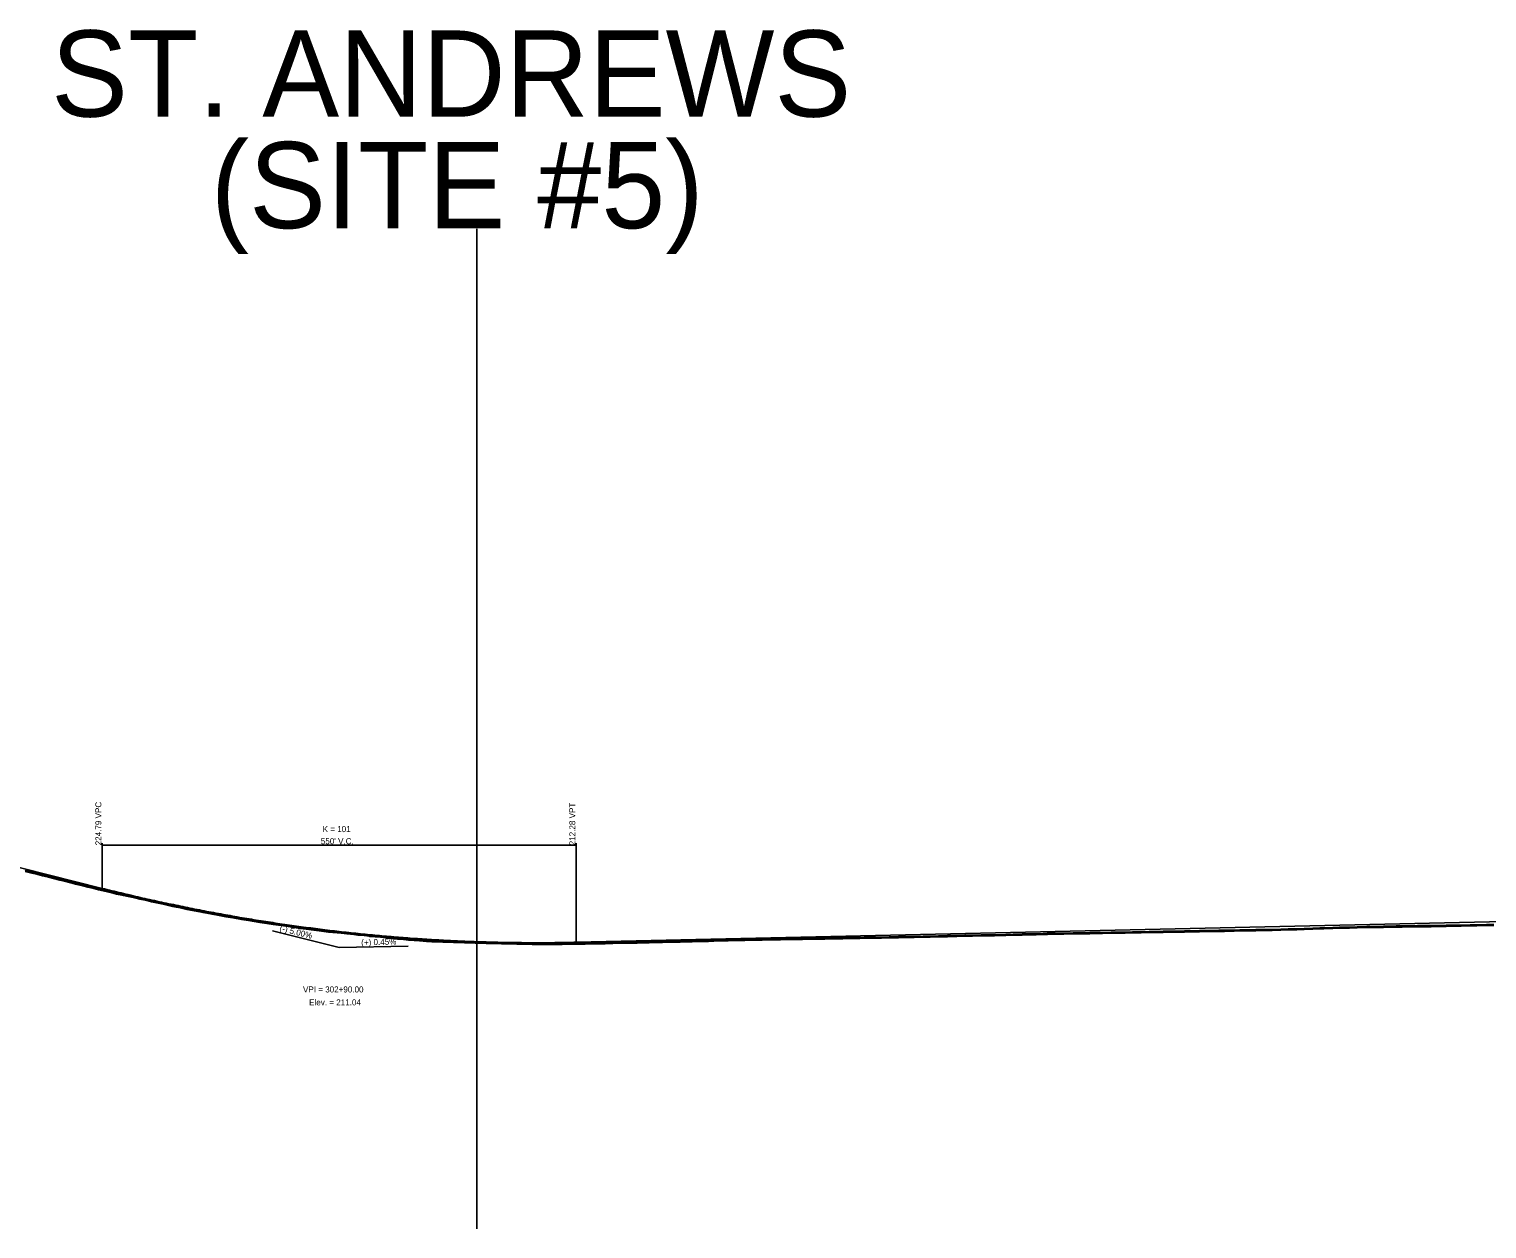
# Model space of a CAD drawing. Extents: x 1876258 to 1926563, y 729739 to 834437.
# Drawn here: x 1908293 to 1909985, y 830733 to 832125 of the extents above; entities that cross this region are included whole.
import ezdxf

# ---------------------------------------------------------------- set-up
doc = ezdxf.new("R2010")
doc.units = 0
for name, color, linetype in [('RD_EX_BldgApp', 7, 'Continuous'), ('RD_EX_H2O_BlueLn', 7, 'Continuous'), ('RD_EX_RailRoad', 7, 'Continuous'), ('RD_HC_Data', 7, 'Continuous'), ('RD_HC_Data_Tic', 7, 'Continuous'), ('RD_HC_TX_Sta50', 7, 'Continuous'), ('RD_PD_ALT5_CL', 7, 'Continuous')]:
    doc.layers.add(name, color=color, linetype=linetype)

msp = doc.modelspace()

# ---------------------------------------------------------------- linework, layer by layer
at = {"layer": 'RD_EX_BldgApp'}
for points in [[(1908288.5, 831148), (1908296.4, 831146), (1908302, 831144.6), (1908308.9, 831142.7), (1908315.8, 831141.1), (1908321.4, 831139.8), (1908328.8, 831137.9), (1908334.1, 831136.6), (1908341.5, 831134.6), (1908347.1, 831133.2), (1908355.7, 831131), (1908361.2, 831129.6), (1908368.2, 831128), (1908373.7, 831126.6), (1908379.1, 831125.4), (1908389.1, 831123), (1908394.7, 831121.7), (1908402.6, 831119.9), (1908408.2, 831118.7), (1908415.8, 831117.1), (1908421.8, 831115.8), (1908429.8, 831114), (1908435.2, 831112.7), (1908442.8, 831111.1), (1908448.6, 831109.9), (1908459.8, 831107.4), (1908464.2, 831106.4), (1908468.6, 831105.5), (1908476.4, 831103.8), (1908487.1, 831101.7), (1908495.2, 831100.1), (1908505.5, 831098.2), (1908513.8, 831096.7), (1908521.6, 831095.3), (1908529.8, 831093.9), (1908539.7, 831092.2), (1908547.8, 831090.9), (1908554.5, 831089.8), (1908561.1, 831088.7), (1908569.1, 831087.4), (1908576.5, 831086.3), (1908585.9, 831085), (1908593.7, 831083.9), (1908600.9, 831082.9), (1908607.9, 831081.8), (1908614.9, 831080.9), (1908623.6, 831079.7), (1908629.8, 831078.9), (1908632.5, 831078.6), (1908640.6, 831077.6), (1908650.8, 831076.6), (1908655.5, 831076.2), (1908662, 831075.4), (1908670, 831074.6), (1908674.9, 831074.1), (1908681.9, 831073.4), (1908687.9, 831072.8), (1908688.5, 831072.6), (1908694.8, 831072), (1908700.9, 831071.5)], [(1908700.9, 831071.5), (1908707.2, 831070.8), (1908716, 831069.9), (1908720.9, 831069.5), (1908727.9, 831068.8), (1908733.7, 831068.3), (1908740.3, 831067.7), (1908746.2, 831067.2), (1908754.5, 831066.7), (1908760.6, 831066.3), (1908823.8, 831064.4), (1908877, 831063.1), (1908886.1, 831063.2), (1908894.4, 831063.2), (1908903.3, 831063.3), (1908911.8, 831063.3), (1908919.4, 831063.4), (1908929.2, 831063.5), (1908938.4, 831063.6), (1908946, 831063.8), (1908955.6, 831064), (1908961.8, 831064.1), (1908970.6, 831064.4), (1908976.3, 831064.5), (1908984.9, 831064.6), (1908992, 831064.7), (1908999, 831064.8), (1909005.1, 831065), (1909012.9, 831065.2), (1909020.5, 831065.3), (1909028.3, 831065.5), (1909035.7, 831065.7), (1909041.9, 831065.8), (1909048.8, 831066), (1909057.6, 831066.2), (1909062.7, 831066.3), (1909070.5, 831066.6), (1909081.6, 831066.8), (1909087.9, 831067), (1909097.3, 831067.2), (1909104.7, 831067.4), (1909111.5, 831067.6), (1909119.2, 831067.8), (1909124, 831067.9), (1909135.5, 831068.1), (1909144.2, 831068.2), (1909155.2, 831068.4), (1909165.4, 831068.6), (1909175.3, 831068.8), (1909183.4, 831069), (1909190.7, 831069.1), (1909200, 831069.3), (1909207.5, 831069.4), (1909210.1, 831069.4), (1909216.8, 831069.5), (1909223.4, 831069.6), (1909231.3, 831069.8), (1909237.7, 831069.9), (1909244.7, 831070), (1909250.8, 831070.1), (1909257.5, 831070.2), (1909262.7, 831070.3), (1909268.9, 831070.5), (1909273.7, 831070.5), (1909282.5, 831070.6), (1909291.6, 831070.7), (1909302.4, 831071), (1909311.4, 831071.2), (1909320.4, 831071.3), (1909330.7, 831071.5), (1909339, 831071.7), (1909348.5, 831071.9), (1909359.1, 831072.1), (1909370.1, 831072.4), (1909379.3, 831072.7), (1909388, 831072.9), (1909398.1, 831073), (1909402.9, 831073.1), (1909413.5, 831073.3), (1909426.8, 831073.6), (1909435.4, 831073.8), (1909445.8, 831074.1), (1909462, 831074.5), (1909470, 831074.7), (1909475.1, 831074.8), (1909487.6, 831075.1), (1909494.2, 831075.2), (1909505, 831075.4), (1909513.3, 831075.5), (1909524.3, 831075.7), (1909532.3, 831075.8), (1909539.1, 831075.9), (1909549, 831076.2), (1909555, 831076.3), (1909565.5, 831076.4), (1909573.7, 831076.5), (1909584, 831076.7), (1909593.3, 831076.9), (1909603.5, 831077.1), (1909609.4, 831077.2), (1909621.2, 831077.4)], [(1909621.2, 831077.4), (1909627.8, 831077.5), (1909634.1, 831077.6), (1909643.4, 831077.8), (1909651.7, 831077.9), (1909658.3, 831078.1), (1909666.4, 831078.3), (1909674, 831078.4), (1909680.5, 831078.4), (1909683.5, 831078.5), (1909691.8, 831078.7), (1909698.6, 831078.9), (1909708.5, 831079), (1909717, 831079.1), (1909727.1, 831079.3), (1909735.9, 831079.4), (1909746.1, 831079.7), (1909754.5, 831080), (1909764.7, 831080.2), (1909773.1, 831080.5), (1909783.1, 831080.8), (1909791.3, 831081.2), (1909796.1, 831081.4), (1909806.4, 831081.7), (1909814.3, 831081.9), (1909825.7, 831082.2), (1909834.6, 831082.4), (1909845.9, 831082.7), (1909854, 831082.9), (1909858, 831082.8), (1909865.1, 831083), (1909875.8, 831083.2), (1909880.1, 831083.3), (1909887, 831083.4), (1909897.2, 831083.6), (1909904.7, 831083.8), (1909914.3, 831083.8), (1909920.4, 831083.8), (1909930.3, 831084), (1909937.8, 831084.2), (1909947.2, 831084.3), (1909955.4, 831084.4), (1909965.6, 831084.6), (1909973.7, 831084.8), (1909984.7, 831085), (1909993.2, 831085.2)]]:
    msp.add_lwpolyline(points, dxfattribs=at)
at = {"layer": 'RD_EX_H2O_BlueLn'}
for p, q in [((1908378.1, 831180.7), (1908378.1, 831128.2)), ((1908378.1, 831178.2), (1908928.1, 831178.2)), ((1908928.1, 831180.7), (1908928.1, 831065.7))]:
    msp.add_line(p, q, dxfattribs=at)
at = {"layer": 'RD_HC_Data_Tic'}
msp.add_line((1908812.7, 830733.3), (1908812.7, 831893.4), dxfattribs=at)
msp.add_lwpolyline([(1908288.8, 831149.2), (1908296.7, 831147.2), (1908302.3, 831145.8), (1908309.2, 831144), (1908316, 831142.3), (1908321.7, 831141), (1908329.1, 831139.1), (1908334.4, 831137.8), (1908341.8, 831135.8), (1908347.4, 831134.4), (1908356, 831132.2), (1908361.5, 831130.8), (1908368.5, 831129.2), (1908374, 831127.9), (1908379.4, 831126.6), (1908389.3, 831124.2), (1908395, 831123), (1908402.9, 831121.2), (1908408.4, 831119.9), (1908416.1, 831118.3), (1908422.1, 831117.1), (1908430.1, 831115.2), (1908435.5, 831113.9), (1908443, 831112.4), (1908448.9, 831111.1), (1908460, 831108.6), (1908464.5, 831107.6), (1908468.9, 831106.7), (1908476.6, 831105), (1908487.4, 831102.9), (1908495.4, 831101.4), (1908505.7, 831099.4), (1908514, 831097.9), (1908521.8, 831096.5), (1908530, 831095.1), (1908539.9, 831093.5), (1908548, 831092.2), (1908554.7, 831091), (1908561.3, 831089.9), (1908569.3, 831088.6), (1908576.7, 831087.5), (1908586.1, 831086.2), (1908593.8, 831085.1), (1908601, 831084.1), (1908608.1, 831083.1), (1908615.1, 831082.1), (1908623.7, 831080.9), (1908629.9, 831080.1), (1908632.6, 831079.9), (1908640.8, 831078.9), (1908650.9, 831077.8), (1908655.7, 831077.4), (1908662.1, 831076.6), (1908670.1, 831075.8), (1908675, 831075.4), (1908682, 831074.7), (1908688.2, 831074), (1908688.7, 831073.8), (1908695, 831073.3), (1908701, 831072.7), (1908707.3, 831072), (1908716.1, 831071.2), (1908721.1, 831070.7), (1908728, 831070.1), (1908733.8, 831069.5), (1908740.4, 831069), (1908746.3, 831068.5), (1908754.6, 831067.9), (1908760.7, 831067.5), (1908823.8, 831065.7), (1908877, 831064.3), (1908886.1, 831064.4), (1908894.4, 831064.4), (1908903.3, 831064.5), (1908911.8, 831064.6), (1908919.4, 831064.7), (1908929.2, 831064.8), (1908938.3, 831064.9), (1908946, 831065.1), (1908955.5, 831065.3), (1908961.8, 831065.4), (1908970.6, 831065.6), (1908976.2, 831065.7), (1908984.9, 831065.9), (1908991.9, 831066), (1908998.9, 831066.1), (1909005, 831066.3), (1909012.9, 831066.4), (1909020.5, 831066.6), (1909028.3, 831066.7), (1909035.6, 831066.9), (1909041.9, 831067.1), (1909048.8, 831067.2), (1909057.6, 831067.5), (1909062.6, 831067.6), (1909070.5, 831067.8), (1909081.6, 831068.1), (1909087.8, 831068.2), (1909097.3, 831068.5), (1909104.6, 831068.7), (1909111.4, 831068.8), (1909119.1, 831069.1), (1909124, 831069.2), (1909135.4, 831069.3), (1909144.2, 831069.5), (1909155.2, 831069.6), (1909165.3, 831069.8), (1909175.3, 831070), (1909183.4, 831070.2), (1909190.6, 831070.4), (1909200, 831070.6), (1909207.5, 831070.6), (1909210.1, 831070.6), (1909216.8, 831070.7), (1909223.4, 831070.8), (1909231.2, 831071), (1909237.7, 831071.1), (1909244.6, 831071.2), (1909250.8, 831071.3), (1909257.5, 831071.4), (1909262.6, 831071.5), (1909268.8, 831071.7), (1909273.6, 831071.7), (1909282.4, 831071.8), (1909291.6, 831072), (1909302.4, 831072.3), (1909311.4, 831072.4), (1909320.4, 831072.6), (1909330.7, 831072.8), (1909339, 831072.9), (1909348.5, 831073.1), (1909359.1, 831073.4), (1909370, 831073.7), (1909379.3, 831073.9), (1909388, 831074.1), (1909398.1, 831074.3), (1909402.9, 831074.4), (1909413.4, 831074.5), (1909426.7, 831074.8), (1909435.4, 831075.1), (1909445.8, 831075.4), (1909462, 831075.7), (1909470, 831075.9), (1909475, 831076.1), (1909487.6, 831076.3), (1909494.2, 831076.4), (1909505, 831076.7), (1909513.3, 831076.7), (1909524.3, 831076.9), (1909532.3, 831077), (1909539.1, 831077.2), (1909549, 831077.5), (1909555, 831077.5), (1909565.5, 831077.6), (1909573.7, 831077.8), (1909584, 831078), (1909593.3, 831078.1), (1909603.4, 831078.3), (1909609.4, 831078.5), (1909621.1, 831078.6), (1909627.7, 831078.7), (1909634.1, 831078.8), (1909643.4, 831079), (1909651.7, 831079.2), (1909658.3, 831079.4), (1909666.4, 831079.5), (1909673.9, 831079.6), (1909680.5, 831079.7), (1909683.5, 831079.7), (1909691.8, 831079.9), (1909698.5, 831080.1), (1909708.5, 831080.3), (1909717, 831080.4), (1909727.1, 831080.5), (1909735.9, 831080.7), (1909746, 831081), (1909754.5, 831081.2), (1909764.7, 831081.5), (1909773.1, 831081.8), (1909783.1, 831082.1), (1909791.3, 831082.5), (1909796, 831082.6), (1909806.4, 831082.9), (1909814.3, 831083.2), (1909825.7, 831083.4), (1909834.5, 831083.7), (1909845.9, 831083.9), (1909853.9, 831084.1), (1909858, 831084.1), (1909865, 831084.3), (1909875.7, 831084.4), (1909880, 831084.6), (1909887, 831084.6), (1909897.1, 831084.9), (1909904.7, 831085), (1909914.3, 831085.1), (1909920.4, 831085.1), (1909930.2, 831085.3), (1909937.8, 831085.4), (1909947.2, 831085.5), (1909955.4, 831085.7), (1909965.6, 831085.9), (1909973.7, 831086), (1909984.6, 831086.2), (1909993.2, 831086.4)], dxfattribs=at)
at = {"layer": 'RD_HC_TX_Sta50'}
for p in [(1908575.5, 831078.9), (1908733.1, 831061.3)]:
    msp.add_line(p, (1908653.1, 831059.5), dxfattribs=at)
at = {"layer": 'RD_PD_ALT5_CL'}
for p, q in [((1908058.1, 831208.2), (1908378.1, 831128.2)), ((1908928.1, 831065.7), (1910073.1, 831091.5))]:
    msp.add_line(p, q, dxfattribs=at)
msp.add_spline([(1908378.1, 831128.2), (1908389.1, 831125.5), (1908400.1, 831122.9), (1908411.1, 831120.3), (1908422.1, 831117.7), (1908433.1, 831115.2), (1908444.1, 831112.8), (1908455.1, 831110.5), (1908466.1, 831108.2), (1908477.1, 831105.9), (1908488.1, 831103.7), (1908499.1, 831101.6), (1908510.1, 831099.6), (1908521.1, 831097.6), (1908532.1, 831095.6), (1908543.1, 831093.7), (1908554.1, 831091.9), (1908565.1, 831090.2), (1908576.1, 831088.5), (1908587.1, 831086.8), (1908598.1, 831085.2), (1908609.1, 831083.7), (1908620.1, 831082.3), (1908631.1, 831080.9), (1908642.1, 831079.5), (1908653.1, 831078.2), (1908664.1, 831077), (1908675.1, 831075.8), (1908686.1, 831074.7), (1908697.1, 831073.7), (1908708.1, 831072.7), (1908719.1, 831071.8), (1908730.1, 831070.9), (1908741.1, 831070.1), (1908752.1, 831069.4), (1908763.1, 831068.7), (1908774.1, 831068.1), (1908785.1, 831067.5), (1908796.1, 831067), (1908807.1, 831066.6), (1908818.1, 831066.2), (1908829.1, 831065.9), (1908840.1, 831065.6), (1908851.1, 831065.4), (1908862.1, 831065.3), (1908873.1, 831065.2), (1908884.1, 831065.2), (1908895.1, 831065.2), (1908906.1, 831065.3), (1908917.1, 831065.5), (1908928.1, 831065.7)], degree=3, dxfattribs=at)

# ---------------------------------------------------------------- texts
at = {"layer": 'RD_EX_H2O_BlueLn'}
for s, p in [('K = 101', (1908633.9, 831193.5)), ("550' V.C.", (1908631.8, 831179.5))]:
    msp.add_text(s, height=7, dxfattribs=at).set_placement(p)
at = {"layer": 'RD_EX_RailRoad'}
for s, p in [('224.79 VPC', (1908377.1, 831178.2)), ('212.28 VPT', (1908927.1, 831178.2))]:
    msp.add_text(s, height=7, rotation=90, dxfattribs=at).set_placement(p)
at = {"layer": 'RD_HC_Data'}
for s, p in [('VPI = 302+90.00', (1908611.1, 831007.5)), ('Elev. = 211.04', (1908618.2, 830992.5))]:
    msp.add_text(s, height=7, dxfattribs=at).set_placement(p)
at = {"layer": 'RD_HC_Data_Tic'}
for s, p in [('ST. ANDREWS', (1908318.7, 832023.5)), ('(SITE #5)', (1908504, 831894.1))]:
    msp.add_text(s, height=100, dxfattribs=at).set_placement(p)
at = {"layer": 'RD_HC_TX_Sta50'}
for s, rotation, p in [('(-) 5.00%', 345.9638, (1908583.4, 831079)), ('(+) 0.45%', 1.2894, (1908678.7, 831062.1))]:
    msp.add_text(s, height=7, rotation=rotation, dxfattribs=at).set_placement(p)

doc.saveas('drawing.dxf')
